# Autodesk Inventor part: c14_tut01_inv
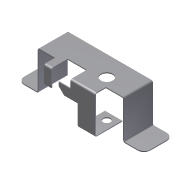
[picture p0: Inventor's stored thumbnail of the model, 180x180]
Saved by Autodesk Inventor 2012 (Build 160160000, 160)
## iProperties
Created: 2010-05
Part Number: c14_tut01_inv
Material: Default
Document SubType Name: Sheet Metal
Designer: CADSoft
Density: 1 g/cm^3
Flat Pattern Width: 11.2524 cm
Flat Pattern Length: 22.0048 cm
Flat Pattern Area: 247.606 cm^2
Sheet Metal Rule: Default_mm
Sheet Metal Width: 112.524 mm
Sheet Metal Length: 220.048 mm
Sheet Metal Area: 24760.634 mm^2
Author: CADSoft
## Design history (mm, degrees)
node "Face1"
  sketch "Sketch1"
    geometry: L1 (0, -18)-(-8, -18); L2 (-8, -18)-(-8, -6); L3 (-8, -6)-(-27, -6); L4 (-27, -6)-(-27, 26); L5 (-27, 26)-(68, 26); L6 (68, 26)-(68, -6); L7 (68, -6)-(48, -6); L8 (48, -6)-(48, -18); L9 (48, -18)-(21, -18); L10 (21, -18)-(21, 0); L11 (21, 0)-(0, 0); L12 (0, 0)-(0, -18); 1 further point
    constraints: 24 end point, 9 parallel, 1 coincident, 1 collinear, 1 horizontal, 1 perpendicular
    dimensions: "d0" = 95 distance of L4.end L5.end; "d1" = 26 distance between parallel lines of L5 L11; "d2" = 32 distance of L3.end L4.end; "d3" = 44 distance between parallel lines of L1 L5; "d4" = 19 distance of L2.end L3.end; "d5" = 8 distance of L1.start L1.end; "d6" = 27 distance of L8.end L9.end; "d7" = 20 distance of L6.end L7.end; "d8" = 32 distance of L5.end L6.end; "d9" = 44 distance between parallel lines of L9 L5
sketch "Sketch2"
  geometry: L1 (20, -41)-(42, -41); L2 (20, 0)-(0, 0) reference; L3 (20, 0)-(20, -41); 1 further point
  constraints: 4 end point, 1 perpendicular
  dimensions: "d13" = 22 distance of L1.start L1.end; "d37" = 41 distance between parallel lines of L1 L2
sketch "Sketch3"
  geometry: L1 (0, -41)-(-22, -41); L2 (19, 0)-(0, 0) reference; L3 (0, -41)-(0, 0); 1 further point
  constraints: 4 end point, 1 perpendicular
  dimensions: "d26" = 22 distance of L1.start L1.end; "d47" = 41 distance of L1.start L2.end
node "Contour Flange3"
node "Contour Flange4"
node "Contour Flange5"
  sketch "Sketch5"
    geometry: L1 (0, 12)-(-1, 12) reference; L2 (-1, 0)-(41, 0); L3 (41, 0)-(41, 30); 1 further point
    constraints: 4 end point, 1 parallel, 1 perpendicular
    dimensions: "d57" = 42 distance of L2.start L2.end; "d58" = 30 distance of L2.end L3.end
sketch "Sketch6"
  geometry: L1 (27, 38)-(27, 0) reference; L2 (-6.407, 21)-(8, 21); L3 (8, 21)-(8, -11.482); L4 (8, -11.482)-(-6.407, -11.482); L5 (-6.407, -11.482)-(-6.407, 21); L6 (0, 40)-(27, 40) reference; 1 further point
  constraints: 8 end point, 2 parallel, 1 horizontal, 1 perpendicular
  dimensions: "d69" = 19 distance between parallel lines of L2 L6; "d70" = 19 distance between parallel lines of L3 L1
cut "Cut1" sketch "Sketch6" dims "d71" = 1 (= Thickness), "d72" = 0
node "Face2"
  sketch "Sketch7"
    geometry: L1 (0, -17)-(-13, -17); L2 (-13, -17)-(-13, -7); L3 (-13, -7)-(0, -7); L4 (0, -7)-(0, -17); 1 further point
    constraints: 8 end point, 2 parallel, 1 horizontal, 1 perpendicular
    dimensions: "d73" = 13 distance of L2.end L3.end; "d74" = 10 distance of L1.end L2.end
feature "Corner Chamfer1" dims "d80" = 6, "d81" = 6, angle "d82" = 45 deg
node "Flange1"
feature "Corner Round1" dims "d93" = 7, "d94" = 7
hole "Hole1" diameter "d97" = 13; stored, may be unused: countersink angle "d101" = 90 deg, drill point angle "d103" = 118 deg; dims "d95" = 22, "d96" = 29, "d98" = 6, "d99" = 4, "d100" = 2, "d102" = 1 (= Thickness)
hole "Hole2" diameter "d106" = 8; stored, may be unused: countersink angle "d110" = 90 deg, drill point angle "d112" = 118 deg; dims "d104" = 22, "d105" = 29, "d107" = 6, "d108" = 4, "d109" = 2, "d111" = 1 (= Thickness)
body "Solid1"
face "Plate1" dims "Thickness" = 1 (derived)
face "Plate4" dims "d38" = 1 (= BendReliefWidth), "d39" = 0.5 (= BendReliefDepth), "d40" = 2 (= MinimumRemnant), "d41" = 1 (= BendRadius), "d42" = 1 (= BendRadius), "d43" = 1, "d44" = 4 (= CornerReliefSize), "d45" = 1 (= GapSize), "d46" = 1 (= JacobiRadiusSize), "SeamGap" = 0.01, "Thickness" = 1 (derived)
bend "Bend3" dims "d38" = 1 (= BendReliefWidth), "d39" = 0.5 (= BendReliefDepth), "d40" = 2 (= MinimumRemnant), "d41" = 1 (= BendRadius), "d42" = 1 (= BendRadius), "d43" = 1, "SeamGap" = 0.01, "Thickness" = 1 (derived)
feature "Corner3" dims "d43" = 1, "d44" = 4 (= CornerReliefSize), "d45" = 1 (= GapSize), "d46" = 1 (= JacobiRadiusSize)
face "Plate5" dims "d48" = 1 (= BendReliefWidth), "d49" = 0.5 (= BendReliefDepth), "d50" = 2 (= MinimumRemnant), "d51" = 1 (= BendRadius), "d52" = 1 (= BendRadius), "d53" = 1, "d54" = 4 (= CornerReliefSize), "d55" = 1 (= GapSize), "d56" = 1 (= JacobiRadiusSize), "SeamGap" = 0.01, "Thickness" = 1 (derived)
bend "Bend4" dims "d48" = 1 (= BendReliefWidth), "d49" = 0.5 (= BendReliefDepth), "d50" = 2 (= MinimumRemnant), "d51" = 1 (= BendRadius), "d52" = 1 (= BendRadius), "d53" = 1, "SeamGap" = 0.01, "Thickness" = 1 (derived)
feature "Corner4" dims "d53" = 1, "d54" = 4 (= CornerReliefSize), "d55" = 1 (= GapSize), "d56" = 1 (= JacobiRadiusSize)
face "Plate6" dims "d60" = 1 (= BendReliefWidth), "d61" = 0.5 (= BendReliefDepth), "d62" = 2 (= MinimumRemnant), "d63" = 1 (= BendRadius), "d64" = 1 (= BendRadius), "d65" = 1, "d66" = 4 (= CornerReliefSize), "d67" = 1 (= GapSize), "d68" = 1 (= JacobiRadiusSize), "SeamGap" = 0.01, "Thickness" = 1 (derived)
bend "Bend5" dims "d60" = 1 (= BendReliefWidth), "d61" = 0.5 (= BendReliefDepth), "d62" = 2 (= MinimumRemnant), "d63" = 1 (= BendRadius), "d64" = 1 (= BendRadius), "d65" = 1, "SeamGap" = 0.01, "Thickness" = 1 (derived)
feature "Corner5" dims "d65" = 1, "d66" = 4 (= CornerReliefSize), "d67" = 1 (= GapSize), "d68" = 1 (= JacobiRadiusSize)
face "Plate7" dims "d75" = 1 (= BendRadius), "d76" = 1 (= BendReliefWidth), "d78" = 2 (= MinimumRemnant), "Thickness" = 1 (derived)
bend "Bend6" dims "d75" = 1 (= BendRadius), "d76" = 1 (= BendReliefWidth), "d77" = 0.5 (= BendReliefDepth), "d78" = 2 (= MinimumRemnant), "d79" = 1 (= BendRadius), "SeamGap" = 0.01, "Thickness" = 1 (derived)
sketch "Sketch8"
  geometry: L1 (0, 19)-(-8, 19); L2 (-8, 19)-(-8, 0); 2 other entities
  constraints: 4 end point, 4 other
face "Plate8" dims "d83" = 1 (= BendReliefWidth), "d84" = 0.5 (= BendReliefDepth), "d85" = 2 (= MinimumRemnant), "d86" = 1 (= BendRadius), "d87" = 19, "d88" = 90 deg, "d89" = 1 (= BendRadius), "d90" = 4 (= CornerReliefSize), "d91" = 1 (= GapSize), "d92" = 1 (= JacobiRadiusSize), "SeamGap" = 0.01, "Thickness" = 1 (derived)
bend "Bend7" dims "d83" = 1 (= BendReliefWidth), "d84" = 0.5 (= BendReliefDepth), "d85" = 2 (= MinimumRemnant), "d86" = 1 (= BendRadius), "d87" = 19, "d88" = 90 deg, "d89" = 1 (= BendRadius), "SeamGap" = 0.01, "Thickness" = 1 (derived)
feature "Corner6" dims "d87" = 19, "d88" = 90 deg, "d90" = 4 (= CornerReliefSize), "d91" = 1 (= GapSize), "d92" = 1 (= JacobiRadiusSize)
feature "Definition1"
other parameters: "BendRadius" = 1 (= Thickness), "BendReliefWidth" = 1 (= Thickness), "BendReliefDepth" = 0.5 (= 0.5 x Thickness), "CornerReliefSize" = 4 (= 4 x Thickness), "MinimumRemnant" = 2 (= 2 x Thickness), "TransitionRadius" = 1 (= BendRadius), "JacobiRadiusSize" = 1 (= BendRadius), "GapSize" = 1 (= Thickness), "d10" = 1 (= BendRadius), "BendRadius" = 1, "BendReliefDepth" = 0.5, "BendReliefWidth" = 1, "CornerReliefSize" = 4, "GapSize" = 1, "JacobiRadiusSize" = 1, "MinimumRemnant" = 2, "Thickness" = 1, "TransitionRadius" = 1
